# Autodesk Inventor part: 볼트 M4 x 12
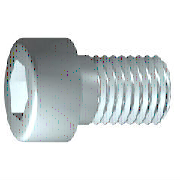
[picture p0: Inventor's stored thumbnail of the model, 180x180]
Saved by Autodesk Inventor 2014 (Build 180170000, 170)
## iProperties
IsCustomPart: 1
Created: 2012-02
Part Number: 볼트 M4 x 12
Material: 스테인리스강
Description: 6각 소켓 머리 캡 나사
Document SubType Name: Modeling
Standard: ISO 4762
Designer: mduedu
Standard Revision: Fourth edition 2004-03-01
Standards Organization: ISO
Language: ko-KR
Size Designation: M4 x 12
Categories: <MemberInstance><Categories><Category DisplayName="조임쇠" InternalName="e4da775c-781d-43d5-af7c-5136215cf5a6" Mnemonic="FSTN"><Category DisplayName="볼트" InternalN
Density: 8.08 g/cm^3
Mass: 2.29719 g
Surface Area: 3.30853 cm^2
Volume: 0.284306 cm^3
Appearance: 반광택
Author: mduedu
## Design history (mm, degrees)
sketch "스케치1"
  geometry: L1 (-1, 0)-(12, 0); L2 (12, 0)-(12, 2); L3 (12, 2)-(1.75, 2); L4 (1.75, 2)-(1.32, 2); L5 (1.32, 2)-(0, 2); L6 (0, 2)-(0, 3.5); L7 (0, 3.5)-(-4, 3.5); L8 (-4, 3.5)-(-4, 1.732); L9 (-4, 1.732)-(-2, 1.732); L10 (-2, 1.732)-(-1, 0); L11 (-7.2, 0)-(15.2, 0) reference; L12 (0, -0.7)-(0, 4.2) reference; L13 (1.75, 2)-(0, 2)
  constraints: 22 end point, 6 parallel, 2 collinear, 2 perpendicular, 1 horizontal, 1 point on line
  dimensions: "d1" = 10.25 distance from line of L3.end L2 (= GEL); "d2" = 0.42952 distance of L4.end L3.end (computed from GAL); "d3" = 4 distance between parallel lines of L8 L6 (= KOH); "d4" = 2 distance of L8.end L9.end (= INTI); "d5" = 60 deg angle of L10 L1; "d6" = 4 diameter of L3 L1 (= GD); "d7" = 4 diameter of L5 L1 (= BDM); "d8" = 3.4641 diameter of L9 L1 (= 1.1547 x SW); "d9" = 7 diameter of L7 L1 (= KOD); "d26" = 12 distance between parallel lines of L12 L2 (= NLG)
revolve "본체" sketch "스케치1" stored, may be unused: angle "d10" = 90 deg
sketch "스케치2"
  geometry: L1 (0, -4.9)-(0, 4.9) reference; L2 (-4.9, 0)-(4.9, 0) reference; L3 (1.732, 0)-(0.866, -1.5); L4 (0.866, -1.5)-(-0.866, -1.5); L5 (-0.866, -1.5)-(-1.732, 0); L6 (-1.732, 0)-(-0.866, 1.5); L7 (-0.866, 1.5)-(0.866, 1.5); L8 (0.866, 1.5)-(1.732, 0); 2 further points
  constraints: 12 end point, 1 coincident, 1 horizontal alignment, 1 point on line, 12 other
extrude "슬롯" join sketch "스케치2" stored distance "d11" = 10; taper "d12" = 0 deg
workplane "Work Plane1"
fillet "Fillet2" dims "d30" = 0.1 (= R)
body "Solid1"
fillet "모깎기1" dims "d17" = 0.4 (= RR)
feature "스레드" dims "d13" = 10.25 (= GEL), "d14" = 0
chamfer "모따기1" distance "d15" = 0.42941 (= -0.5 x SPD + 0.5 x GD); stored, may be unused: second distance "d16" = 0.42941 (= GUL), angle "d27" = 45 deg
other parameters: "GD" = 4 [user parameter; used in 2 equation terms], "NLG" = 12 [user parameter; used in 1 equation term], "GEL" = 10.25 [user parameter; used in 2 equation terms], "KOD" = 7 [user parameter; used in 1 equation term], "KOH" = 4 [user parameter; used in 1 equation term], "INTI" = 2 [user parameter; used in 1 equation term], "GAL" = 0.42941 (= 0.61345 x PTC) [user parameter; used in 1 equation term], "GUL" = 0.42941 (= 0.61345 x PTC) [user parameter; used in 1 equation term], "BDM" = 4 (= NND) [user parameter; used in 1 equation term], "SW" = 3 [user parameter; used in 2 equation terms], "RR" = 0.4 [user parameter; used in 1 equation term], "SPD" = 3.14117 (= NND - 1.2269 x PTC) [user parameter; used in 1 equation term], "d19" = 0, "d28" = 0, "d29" = 0, "R" = 0.1 [user parameter; used in 1 equation term], "TOA" = 30 deg [user parameter], "GD1" = 3.14117 (= THREADDIA - 1.2269 x PTC) [user parameter], "THREADDIA" = 4 [user parameter; used in 1 equation term], "FAWI" = 45 deg [user parameter], "TPU" = 14.28571 (computed from PTC) [user parameter], "PTC" = 0.7 [user parameter; used in 5 equation terms], "NND" = 4 [user parameter; used in 2 equation terms], "E0" = 3.465 (= 1.155 x SW) [user parameter]
